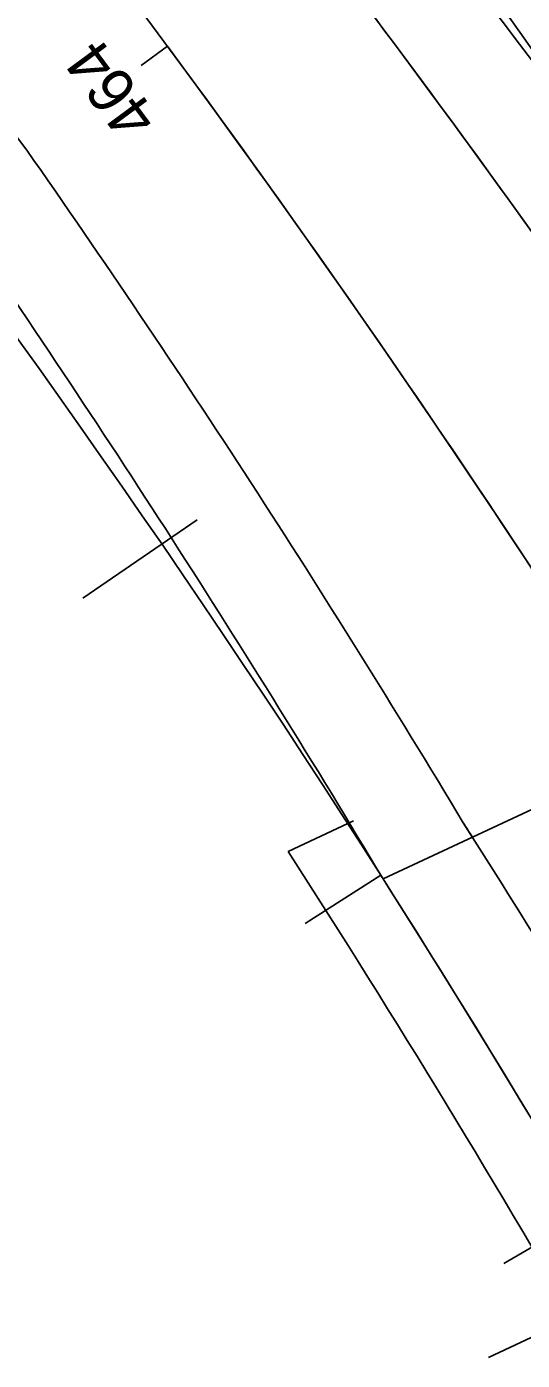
# Model space of a CAD drawing. Extents: x 2355002 to 2355569, y 708374 to 709566.
# Drawn here: x 2355274.1 to 2355304.5, y 709345.9 to 709427.8 of the extents above; entities that cross this region are included whole.
import ezdxf

# ---------------------------------------------------------------- set-up
doc = ezdxf.new("R2010")
doc.units = 0
for name, color, linetype in [('BR_X_Gen_Approach_Slab', 7, 'Continuous'), ('DR_X_Underdrain', 7, 'Continuous'), ('DT_X_Slope_Break_Line', 7, 'Continuous'), ('PM_X_CL_Double_Solid', 7, 'Continuous'), ('PM_X_Edge_Line', 7, 'Continuous'), ('PV_X_EOP', 7, 'Continuous'), ('RD_X_Fence', 7, 'Continuous'), ('RD_X_GR_Lt', 7, 'Continuous'), ('RD_X_Wall', 7, 'Continuous'), ('VG_X_Tree_Line_Rt', 7, 'Continuous')]:
    doc.layers.add(name, color=color, linetype=linetype)

msp = doc.modelspace()

# ---------------------------------------------------------------- linework, layer by layer
at = {"layer": 'BR_X_Gen_Approach_Slab'}
msp.add_line((2355295.985, 709375.458), (2355328.849, 709390.839), dxfattribs=at)
msp.add_arc((2354704.756, 708999.812), 700.472, 29.975428, 32.430394, dxfattribs=at)
at = {"layer": 'DR_X_Underdrain'}
for p, q in [((2355277.574, 709392.697), (2355284.583, 709397.505)), ((2355291.203, 709372.728), (2355295.845, 709375.679)), ((2355303.391, 709351.847), (2355308.563, 709354.888))]:
    msp.add_line(p, q, dxfattribs=at)
at = {"layer": 'DT_X_Slope_Break_Line'}
msp.add_line((2355309.464, 709349.372), (2355302.456, 709346.092), dxfattribs=at)
at = {"layer": 'PM_X_CL_Double_Solid'}
for start, end in [(29.692057, 41.655322), (29.69174, 36.439187)]:
    msp.add_arc((2354704.755, 708999.811), 718.474, start, end, dxfattribs=at)
at = {"layer": 'PM_X_Edge_Line'}
for centre, radius, start, end in [((2354267.281, 708657.323), 1263.211, 37.150473, 42.321984), ((2354710.315, 708989.774), 731.259, 33.349275, 42.544873), ((2354693.781, 709014.399), 708.142, 30.979282, 34.962109), ((2354704.744, 708999.831), 706.474, 29.689927, 32.450025)]:
    msp.add_arc(centre, radius, start, end, dxfattribs=at)
at = {"layer": 'PV_X_EOP'}
for centre, radius, start, end in [((2354950.618, 709158.747), 443.761, 31.53432, 38.78676), ((2354710.315, 708989.774), 731.259, 33.349275, 37.330648), ((2354693.781, 709014.399), 708.142, 30.979282, 34.962109), ((2354641.479, 708983.659), 762.816, 30.905469, 34.591908), ((2354704.744, 708999.831), 706.474, 32.365816, 32.450025)]:
    msp.add_arc(centre, radius, start, end, dxfattribs=at)
at = {"layer": 'RD_X_Fence'}
msp.add_arc((2354704.744, 708999.831), 700.474, 32.42856, 32.450009, dxfattribs=at)
at = {"layer": 'RD_X_GR_Lt'}
for radius, start, end in [(736.474, 31.79992, 39.579675), (700.474, 30.105407, 41.655322)]:
    msp.add_arc((2354704.755, 708999.811), radius, start, end, dxfattribs=at)
at = {"layer": 'RD_X_Wall'}
msp.add_line((2355282.758, 709426.563), (2355281.149, 709425.375), dxfattribs=at)
msp.add_arc((2354704.755, 708999.811), 718.474, 29.692057, 41.655322, dxfattribs=at)
at = {"layer": 'VG_X_Tree_Line_Rt'}
msp.add_line((2355290.156, 709377.146), (2355294.18, 709379.03), dxfattribs=at)
msp.add_arc((2354704.756, 708999.812), 696.472, 29.797214, 32.804787, dxfattribs=at)

# ---------------------------------------------------------------- texts
at = {"layer": 'RD_X_Wall'}
msp.add_text('464', height=2.8, rotation=126.43919, dxfattribs=at).set_placement((2355282.288, 709422.149))

doc.saveas('drawing.dxf')
